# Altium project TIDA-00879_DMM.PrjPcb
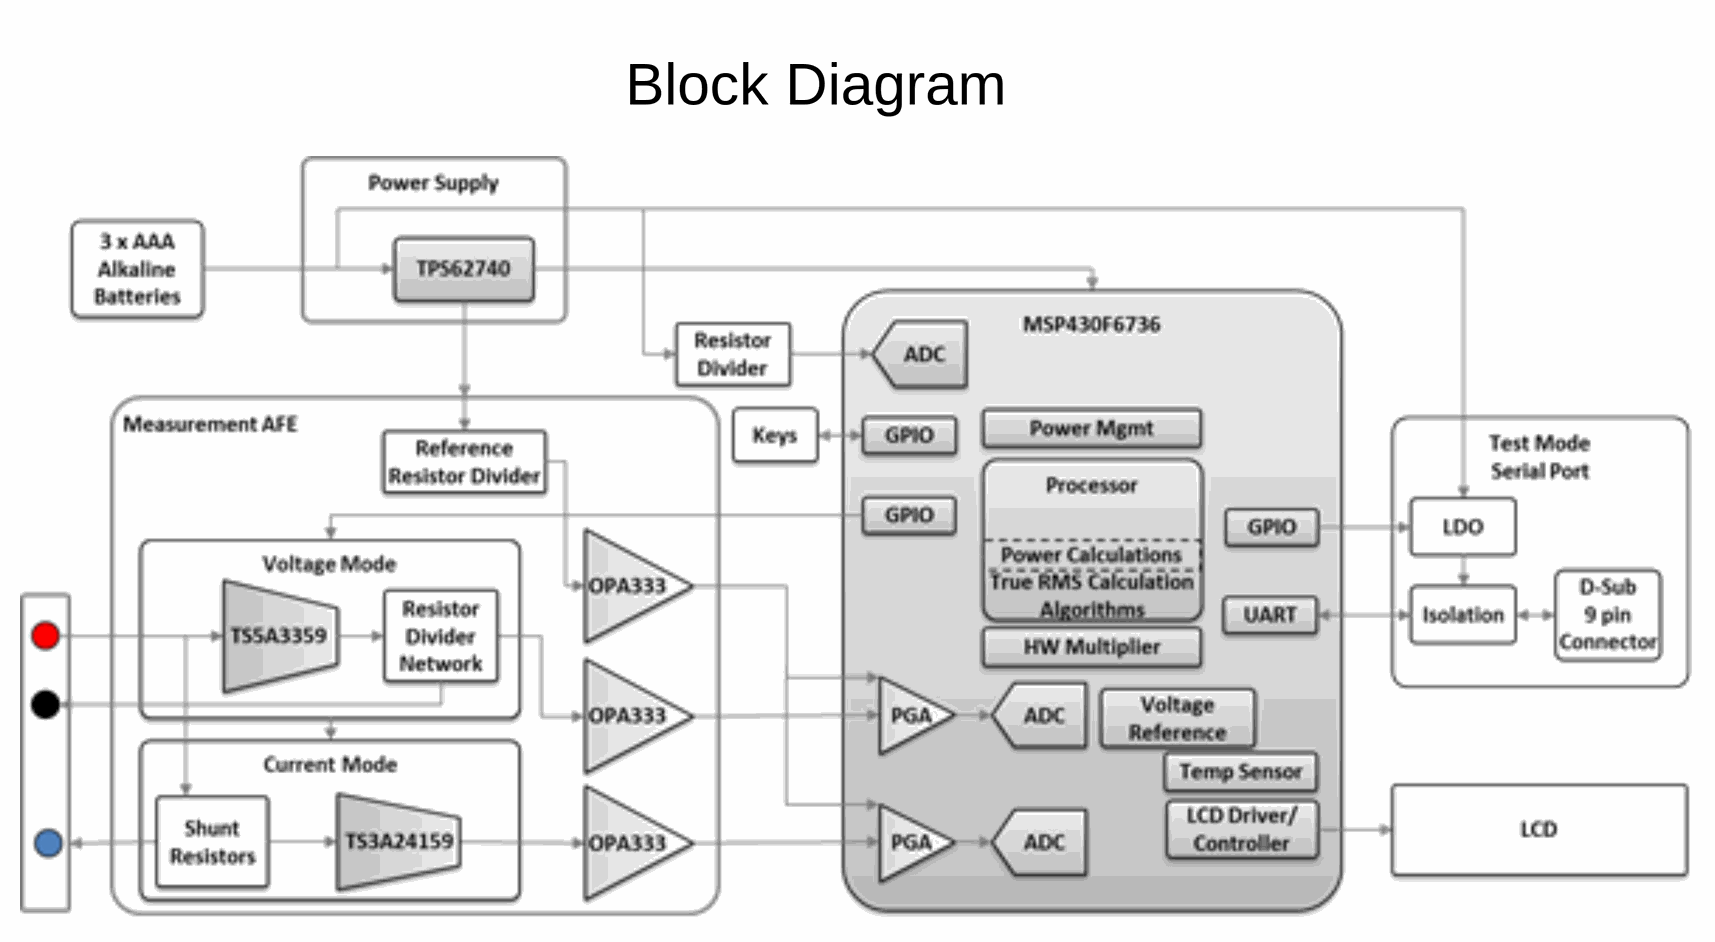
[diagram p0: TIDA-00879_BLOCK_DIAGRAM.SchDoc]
TID: TIDA-00879; TechSupport: http://www.ti.com/support; SCH_Rev: A; PRJ_Title: 4.5 Digit DMM Platform Reference Design; PRJ_Number: TIDA-00879; PRJ_Engineer: Russ Rosenquist; PRJ_Customer: Public Release; PCB_Rev: A; EVM_orderable: N/A; CopyrightYear: 2016
5 sheets, 141 parts. Net scope: flat (ports and power ports of the same name join across sheets).
Board file: TIDA-00879_DMM.PcbDoc
Sheets:
  TIDA-00879_BLOCK_DIAGRAM.SchDoc
  TIDA-00879_MCU.SchDoc
  TIDA-00879_AFE.SchDoc
  TIDA-00879_TEST.SchDoc
  TIDA-00879_MISC.SchDoc

## Sheet TIDA-00879_BLOCK_DIAGRAM.SchDoc: Hardware - Miscellaneous
size 431 x 279 mm; Date: Not shown in title block; ApprovedBy: Not shown in title block; CheckedBy: Not shown in title block; Author: Not shown in title block; CompanyName: Not shown in title block; DrawnBy: Russ Rosenquist; Engineer: Not shown in title block; Organization: Not shown in title block; Address1: Not shown in title block; Address2: Not shown in title block; Address3: Not shown in title block; Address4: Not shown in title block; Revision: Use project parameter SCH_Rev; SheetNumber: 1; SheetTotal: 5; PageSetup: Record=PageOptions¦CenterHorizontal=True¦CenterVertical=True¦PrintScale=1.00¦XCorrection=1.00¦YCorrection=1.00¦PrintKind=0¦BorderSize=5000000¦LeftOffset=0¦BottomOffset=0¦Orientation=2¦PaperLength=1000¦PaperWidth=1000¦Scale=100¦PaperSource=15¦PrintQuality=600¦MediaType=1¦DitherType=10¦PaperKind=Letter¦PrintScaleMode=1

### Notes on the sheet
- Block Diagram

## Sheet TIDA-00879_MCU.SchDoc: MCU & Power Blocks
size 431 x 279 mm; Date: Not shown in title block; ApprovedBy: Not shown in title block; CheckedBy: Not shown in title block; Author: Not shown in title block; CompanyName: Not shown in title block; DrawnBy: Russ Rosenquist; Engineer: Russ Rosenquist; Organization: Not shown in title block; Address1: Not shown in title block; Address2: Not shown in title block; Address3: Not shown in title block; Address4: Not shown in title block; DocumentNumber: 1; Revision: Use project parameter SCH_Rev; SheetNumber: 2; SheetTotal: 5; PageSetup: Record=PageOptions¦CenterHorizontal=True¦CenterVertical=True¦PrintScale=1.00¦XCorrection=1.00¦YCorrection=1.00¦PrintKind=0¦BorderSize=5000000¦LeftOffset=0¦BottomOffset=0¦Orientation=2¦PaperLength=1000¦PaperWidth=1000¦Scale=100¦PaperSource=15¦PrintQuality=600¦MediaType=1¦DitherType=10¦PaperKind=Letter¦PrintScaleMode=1
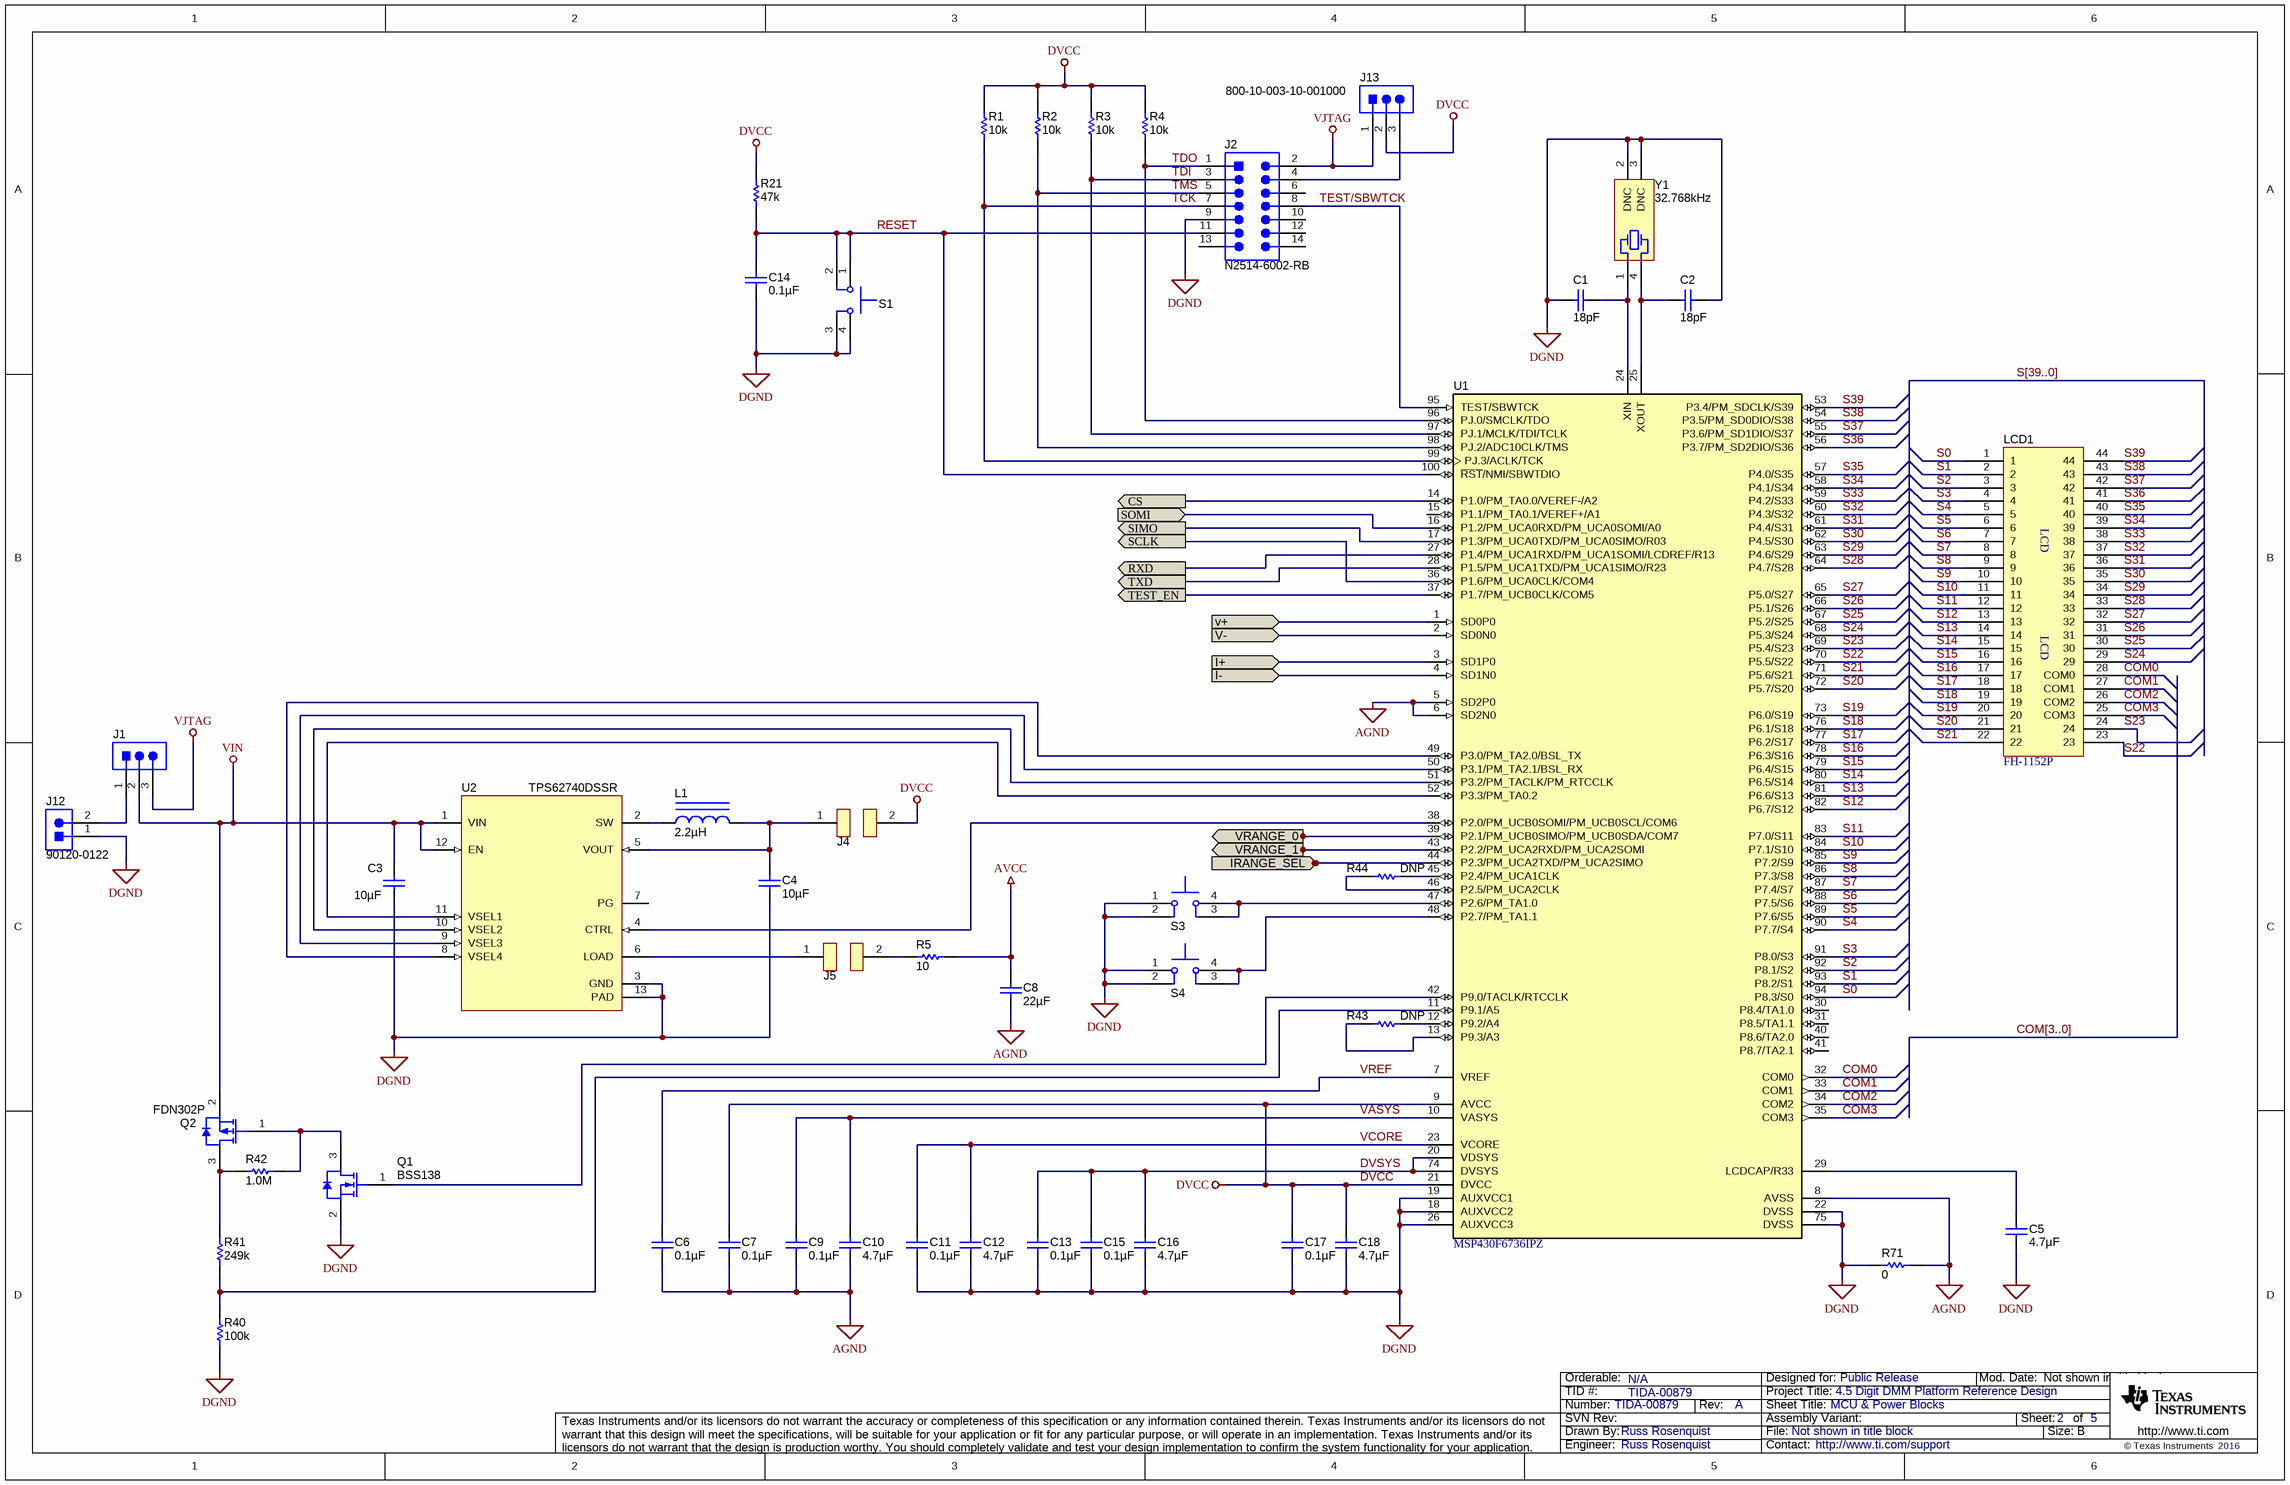
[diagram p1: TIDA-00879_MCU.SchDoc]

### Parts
C1  ValueDisplayed: 18pF  [0402]  (hidden comment: GRM1555C1H180JA01D)
C2  ValueDisplayed: 18pF  [0402]  (hidden comment: GRM1555C1H180JA01D)
C3  ValueDisplayed: 10µF  [0603]  (hidden comment: GRM188R60J106ME84)
C4  ValueDisplayed: 10µF  [0603]  (hidden comment: GRM188R60J106ME84)
C5  ValueDisplayed: 4.7µF  [0402]  (hidden comment: C1005X5R1A475K050BC)
C6  ValueDisplayed: 0.1µF  [0402]  (hidden comment: C1005X5R1A104K050BA)
C7  ValueDisplayed: 0.1µF  [0402]  (hidden comment: C1005X5R1A104K050BA)
C8  ValueDisplayed: 22µF  [0402]  (hidden comment: GRM155R60J226ME11D)
C9  ValueDisplayed: 0.1µF  [0402]  (hidden comment: C1005X5R1A104K050BA)
C10  ValueDisplayed: 4.7µF  [0402]  (hidden comment: C1005X5R1A475K050BC)
C11  ValueDisplayed: 0.1µF  [0402]  (hidden comment: C1005X5R1A104K050BA)
C12  ValueDisplayed: 4.7µF  [0402]  (hidden comment: C1005X5R1A475K050BC)
C13  ValueDisplayed: 0.1µF  [0402]  (hidden comment: C1005X5R1A104K050BA)
C14  ValueDisplayed: 0.1µF  [0603]  (hidden comment: 06033C104JAT2A)
C15  ValueDisplayed: 0.1µF  [0402]  (hidden comment: C1005X5R1A104K050BA)
C16  ValueDisplayed: 4.7µF  [0402]  (hidden comment: C1005X5R1A475K050BC)
C17  ValueDisplayed: 0.1µF  [0402]  (hidden comment: C1005X5R1A104K050BA)
C18  ValueDisplayed: 4.7µF  [0402]  (hidden comment: C1005X5R1A475K050BC)
J1  800-10-003-10-001000  [Mill-Max_800-10-003-10-001000]  (value not drawn)
J2  N2514-6002-RB  [3M_x2514-60xx]
J4  Used in BOM report  [JUMPER_SPCL]  (value not drawn)
J5  Used in BOM report  [JUMPER_SPCL]  (value not drawn)
J12  90120-0122  [CONN_90120-0122]
J13  800-10-003-10-001000  [Mill-Max_800-10-003-10-001000]
L1  ValueDisplayed: 2.2µH  [VLF302515MT]  (hidden comment: VLF302515MT-2R2M)
LCD1  FH-1152P  [FH-1152P]
Q1  BSS138  [SOT-23]
Q2  FDN302P  [SOT-23]
R1  ValueDisplayed: 10k  [0402]  (hidden comment: CRCW040210K0JNED)
R2  ValueDisplayed: 10k  [0402]  (hidden comment: CRCW040210K0JNED)
R3  ValueDisplayed: 10k  [0402]  (hidden comment: CRCW040210K0JNED)
R4  ValueDisplayed: 10k  [0402]  (hidden comment: CRCW040210K0JNED)
R5  ValueDisplayed: 10  [0402]  (hidden comment: CRCW040210R0JNED)
R21  ValueDisplayed: 47k  [0402]  (hidden comment: CRCW040247K0JNED)
R40  ValueDisplayed: 100k  [0402]  (hidden comment: CRCW0402100KFKED)
R41  ValueDisplayed: 249k  [0402]  (hidden comment: CRCW0402249KFKED)
R42  ValueDisplayed: 1.0M  [0402]  (hidden comment: CRCW04021M00JNED)
R43  value DNP  [0402]  (hidden comment: Used in BOM report)
R44  value DNP  [0402]  (hidden comment: Used in BOM report)
R71  ValueDisplayed: 0  [0603]  (hidden comment: CRCW06030000Z0EA)
S1  EVQ-PAD04M  [SW_EVQ-PAD04M]  (value not drawn)
S3  EVQ-PAD04M  [SW_EVQ-PAD04M]  (value not drawn)
S4  EVQ-PAD04M  [SW_EVQ-PAD04M]  (value not drawn)
U1  MSP430F6736IPZ  [PZ0100A_N]
U2  TPS62740DSSR  [DSS0012A]
Y1  Frequency: 32.768kHz  [XTAL_MC-306]  (hidden comment: MC-306 32.768K-E3:ROHS)

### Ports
CS (out), I+ (in), I- (in), IRANGE_SEL (out), RXD, SCLK (out), SIMO, SOMI (in), TEST_EN, TXD, v+ (in), V- (in), VRANGE_0 (out), VRANGE_1 (out)

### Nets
AGND: C6.2 C7.2 C8.1 C9.2 C10.1 R71.1 U1.5(SD2P0) U1.6(SD2N0) U1.8(AVSS)
AVCC: C8.2 R5.2
DGND: C1.1 C2.2 C3.2 C4.2 C5.1 C11.2 C12.2 C13.2 C14.2 C15.2 C16.1 C17.2 C18.1 J2.9 J12.1 Q1.2(S) R40.1 R71.2 S1.3 S1.4 S3.1 S3.2 S4.1 S4.2 U1.18(AUXVCC2) U1.19(AUXVCC1) U1.22(DVSS) U1.26(AUXVCC3) U1.75(DVSS) U2.3(GND) U2.13(PAD) Y1.2(DNC) Y1.3(DNC)
DVCC: C7.1 C17.1 C18.2 J4.2 J13.2 R1.2 R2.2 R3.2 R4.2 R21.2 U1.9(AVCC) U1.21(DVCC)
VIN: C3.1 J1.2 Q2.2(S) U2.1(VIN) U2.12(EN)
VJTAG: J1.3 J2.2 J13.1
COM0: LCD1.28(COM0) U1.32(COM0)
COM1: LCD1.27(COM1) U1.33(COM1)
COM2: LCD1.26(COM2) U1.34(COM2)
COM3: LCD1.25(COM3) U1.35(COM3)
CS: U1.14(P1.0/PM_TA0.0/VEREF-/A2) ; port CS
DVSYS: C13.1 C15.1 C16.2 U1.20(VDSYS) U1.74(DVSYS)
I+: U1.3(SD1P0) ; port I+
I-: U1.4(SD1N0) ; port I-
IRANGE_SEL: U1.44(P2.3/PM_UCA2TXD/PM_UCA2SIMO) ; port IRANGE_SEL
RESET: C14.1 J2.11 R21.1 S1.1 S1.2 U1.100(~{RST}/NMI/SBWTDIO)
RXD: U1.27(P1.4/PM_UCA1RXD/PM_UCA1SOMI/LCDREF/R13) ; port RXD
S0: LCD1.1 U1.94(P8.3/S0)
S1: LCD1.2 U1.93(P8.2/S1)
S2: LCD1.3 U1.92(P8.1/S2)
S3: LCD1.4 U1.91(P8.0/S3)
S4: LCD1.5 U1.90(P7.7/S4)
S5: LCD1.6 U1.89(P7.6/S5)
S6: LCD1.7 U1.88(P7.5/S6)
S7: LCD1.8 U1.87(P7.4/S7)
S8: LCD1.9 U1.86(P7.3/S8)
S9: LCD1.10 U1.85(P7.2/S9)
S10: LCD1.11 U1.84(P7.1/S10)
S11: LCD1.12 U1.83(P7.0/S11)
S12: LCD1.13 U1.82(P6.7/S12)
S13: LCD1.14 U1.81(P6.6/S13)
S14: LCD1.15 U1.80(P6.5/S14)
S15: LCD1.16 U1.79(P6.4/S15)
S16: LCD1.17 U1.78(P6.3/S16)
S17: LCD1.18 U1.77(P6.2/S17)
S18: LCD1.19 U1.76(P6.1/S18)
S19: LCD1.20 U1.73(P6.0/S19)
S20: LCD1.21 U1.72(P5.7/S20)
S21: LCD1.22 U1.71(P5.6/S21)
S22: LCD1.23 U1.70(P5.5/S22)
S23: LCD1.24 U1.69(P5.4/S23)
S24: LCD1.29 U1.68(P5.3/S24)
S25: LCD1.30 U1.67(P5.2/S25)
S26: LCD1.31 U1.66(P5.1/S26)
S27: LCD1.32 U1.65(P5.0/S27)
S28: LCD1.33 U1.64(P4.7/S28)
S29: LCD1.34 U1.63(P4.6/S29)
S30: LCD1.35 U1.62(P4.5/S30)
S31: LCD1.36 U1.61(P4.4/S31)
S32: LCD1.37 U1.60(P4.3/S32)
S33: LCD1.38 U1.59(P4.2/S33)
S34: LCD1.39 U1.58(P4.1/S34)
S35: LCD1.40 U1.57(P4.0/S35)
S36: LCD1.41 U1.56(P3.7/PM_SD2DIO/S36)
S37: LCD1.42 U1.55(P3.6/PM_SD1DIO/S37)
S38: LCD1.43 U1.54(P3.5/PM_SD0DIO/S38)
S39: LCD1.44 U1.53(P3.4/PM_SDCLK/S39)
SCLK: U1.36(P1.6/PM_UCA0CLK/COM4) ; port SCLK
SIMO: U1.17(P1.3/PM_UCA0TXD/PM_UCA0SIMO/R03) ; port SIMO
SOMI: U1.16(P1.2/PM_UCA0RXD/PM_UCA0SOMI/A0) ; port SOMI
TCK: J2.7 R1.1 U1.99(PJ.3/ACLK/TCK)
TDI: J2.3 R3.1 U1.97(PJ.1/MCLK/TDI/TCLK)
TDO: J2.1 R4.1 U1.96(PJ.0/SMCLK/TDO)
TEST/SBWTCK: J2.8 U1.95(TEST/SBWTCK)
TEST_EN: U1.37(P1.7/PM_UCB0CLK/COM5) ; port TEST_EN
TMS: J2.5 R2.1 U1.98(PJ.2/ADC10CLK/TMS)
TXD: U1.28(P1.5/PM_UCA1TXD/PM_UCA1SIMO/R23) ; port TXD
v+: U1.1(SD0P0) ; port v+
V-: U1.2(SD0N0) ; port V-
VASYS: C9.1 C10.2 U1.10(VASYS)
VCORE: C11.1 C12.1 U1.23(VCORE)
VRANGE_0: U1.39(P2.1/PM_UCB0SIMO/PM_UCB0SDA/COM7) ; port VRANGE_0
VRANGE_1: U1.43(P2.2/PM_UCA2RXD/PM_UCA2SOMI) ; port VRANGE_1
VREF: C6.1 U1.7(VREF)
NetC1_2: C1.2 U1.24(XIN) Y1.1
NetC2_1: C2.1 U1.25(XOUT) Y1.4
NetC4_1: C4.1 J4.1 L1.2 U2.5(VOUT)
NetC5_2: C5.2 U1.29(LCDCAP/R33)
NetJ1_1: J1.1 J12.2
NetJ2_4: J2.4 J13.3
NetJ5_1: J5.1 U2.6(LOAD)
NetJ5_2: J5.2 R5.1
NetL1_1: L1.1 U2.2(SW)
NetQ1_1: Q1.1(G) U1.42(P9.0/TACLK/RTCCLK)
NetQ1_3: Q1.3(D) Q2.1(G) R42.1
NetQ2_3: Q2.3(D) R41.2 R42.2
NetR40_2: R40.2 R41.1 U1.11(P9.1/A5)
NetR43_1: R43.1 U1.13(P9.3/A3)
NetR43_2: R43.2 U1.12(P9.2/A4)
NetR44_1: R44.1 U1.46(P2.5/PM_UCA2CLK)
NetR44_2: R44.2 U1.45(P2.4/PM_UCA1CLK)
NetS3_3: S3.3 S3.4 U1.47(P2.6/PM_TA1.0)
NetS4_3: S4.3 S4.4 U1.48(P2.7/PM_TA1.1)
NetU1_38: U1.38(P2.0/PM_UCB0SOMI/PM_UCB0SCL/COM6) U2.4(CTRL)
NetU1_49: U1.49(P3.0/PM_TA2.0/BSL_TX) U2.8(VSEL4)
NetU1_50: U1.50(P3.1/PM_TA2.1/BSL_RX) U2.9(VSEL3)
NetU1_51: U1.51(P3.2/PM_TACLK/PM_RTCCLK) U2.10(VSEL2)
NetU1_52: U1.52(P3.3/PM_TA0.2) U2.11(VSEL1)

Not connected (* = marked no-connect by the designer): J2 6 10 12 13 14; U1 15(P1.1/PM_TA0.1/VEREF+/A1) 30(P8.4/TA1.0) 31(P8.5/TA1.1) 40(P8.6/TA2.0) 41(P8.7/TA2.1); U2 7(PG)

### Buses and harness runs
bus COM[3..0]
bus S[39..0]

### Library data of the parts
C1 C2 = GRM1555C1H180JA01D: CAP, CERM, 18 pF, 50 V, +/- 5%, C0G/NP0, 0402; Manufacturer: MuRata; Polarized: N; CompType: Capacitor; Value: 18pF; U/M: EA; Cap_F: 0.000000000018; Tolerance_%: 5; Value1: Unknown; VDC_V: 50; Value2: 50V; TaMin_C: -55; TaMax_C: 125; AEC Category: Q200
C3 C4 = GRM188R60J106ME84: CAP, CERM, 10 µF, 6.3 V, +/- 20%, X5R, 0603; Manufacturer: MuRata; Polarized: N; CompType: Capacitor; Value: 10uF; U/M: EA; Cap_F: 0.00001; Tolerance_%: 20; Value1: Unknown; VDC_V: 6.3; Value2: 6.3V; TaMin_C: -55; TaMax_C: 85; AEC Category: Q200
C5 C10 C12 C16 C18 = C1005X5R1A475K050BC: CAP, CERM, 4.7 µF, 10 V, +/- 10%, X5R, 0402; Manufacturer: TDK; Polarized: N; CompType: Capacitor; Value: 4.7uF; U/M: EA; Cap_F: 0.0000047; Tolerance_%: 10; Value1: Unknown; Value2: 10V; TaMin_C: -55; TaMax_C: 85; AEC Category: Q200
C6 C7 C9 C11 C13 C15 C17 = C1005X5R1A104K050BA: CAP, CERM, 0.1 µF, 10 V, +/- 10%, X5R, 0402; Manufacturer: TDK; Polarized: N; CompType: Capacitor; Value: 0.1uF; U/M: EA; Cap_F: 0.0000001; Tolerance_%: 10; Value1: Unknown; Value2: 10V; TaMin_C: -55; TaMax_C: 85; AEC Category: Q200
C8 = GRM155R60J226ME11D: CAP, CERM, 22 µF, 6.3 V, +/- 20%, X5R, 0402; Manufacturer: MuRata; Polarized: N; CompType: Capacitor; Value: 22uF; U/M: EA; Cap_F: 0.000022; Tolerance_%: 20; Value1: Unknown; VDC_V: 6.3; Value2: 6.3V; TaMin_C: -55; TaMax_C: 85; AEC Category: Q200
C14 = 06033C104JAT2A: CAP, CERM, 0.1 µF, 25 V, +/- 5%, X7R, 0603; Manufacturer: AVX; Polarized: N; CompType: Capacitor; Value: 0.1uF; U/M: EA; Cap_F: 0.0000001; Tolerance_%: 5; ESR_ohm: 0.05; Value1: 0.05 ohm; VDC_V: 25; Value2: 25V; TaMin_C: -55; TaMax_C: 125; AEC Category: Q200
J1 J13 = 800-10-003-10-001000: Header, 100mil, 3x1, TH; Manufacturer: Mill-Max; SymbolCreator: a0799628
J2 = N2514-6002-RB: Header (shrouded), 100mil, 7x2, Gold, TH; Manufacturer: 3M; SymbolCreator: a0412235
J4 J5 = Jumper_SPCL: SymbolVersion: use current date i.e. 2008-05-20; SymbolCreator: Use a-id; CompType: Used in some BOM reports.  Useful for finding later.; U/M: EA, IN, or GM
J12 = 90120-0122: Header, 100mil, 2x1, Tin, TH; Manufacturer: Molex; SymbolCreator: a0412235
L1 = VLF302515MT-2R2M: Inductor, Shielded, Ferrite, 2.2 µH, 1.57 A, 0.042 ohm, SMD; Manufacturer: TDK; Value: 2.2uH; Ind_H: 2.2E-6; Imax_A: 1.57; Irms: 2.71A @ 40C rise; Isat: 1.57A @ 30% inductance drop; DCR_ohm: 0.042; Value2: 1.57A; AEC Category: Q200
LCD1 = FH-1152P: 160 segment LCD; PartNumber: Supplied by TI; Manufacturer: Custom
Q1 = BSS138: MOSFET, N-CH, 50 V, 0.22 A, SOT-23; Manufacturer: Fairchild Semiconductor; Alternate Manufacturer: None; U/M: EA; ChType: N; Value: 50V; VdsMax_V: 50; Value1: 6 ohm; Rdson45_ohm: 6; Value2: 1.7 nC; QgTyp_nC: 1.7; Vgs_V: 20; IdsMax_A: 0.22; AEC Category: Q101
Q2 = FDN302P: MOSFET, P-CH, -20 V, -2.4 A, SOT-23; Manufacturer: Fairchild Semiconductor; Alternate Manufacturer: None; U/M: EA; ChType: P; Value: -20V; Value1: 0.055 ohm; Rdson45_ohm: 0.055; Value2: 9 nC; QgTyp_nC: 9; Vgs_V: -12; AEC Category: Q101
R1-R4 = CRCW040210K0JNED: RES, 10 k, 5%, 0.063 W, 0402; Manufacturer: Vishay-Dale; CompType: Resistor; Value: 10k; Res_ohm: 10000; Value_Code: 10k0; Tolerance_%: 5; Power_W: 0.063; Value2: 0.063W; VDC_V: 50; TempCo: 200 ppm/C; EIA_Code: E24; U/M: EA; AEC Category: Q200
R5 = CRCW040210R0JNED: RES, 10, 5%, 0.063 W, 0402; Manufacturer: Vishay-Dale; CompType: Resistor; Value: 10; Value_Code: 10R0; Tolerance_%: 5; Power_W: 0.063; Value2: 0.063W; VDC_V: 50; TempCo: 200 ppm/C; EIA_Code: E24; U/M: EA; AEC Category: Q200
R21 = CRCW040247K0JNED: RES, 47 k, 5%, 0.063 W, 0402; Manufacturer: Vishay-Dale; CompType: Resistor; Value: 47k; Res_ohm: 47000; Value_Code: 47k0; Tolerance_%: 5; Power_W: 0.063; Value2: 0.063W; VDC_V: 50; TempCo: 200 ppm/C; EIA_Code: E24; U/M: EA; AEC Category: Q200
R40 = CRCW0402100KFKED: RES, 100 k, 1%, 0.063 W, 0402; Manufacturer: Vishay-Dale; CompType: Resistor; Value: 100k; Res_ohm: 100000; Tolerance_%: 1; Power_W: 0.063; Value2: 0.063W; VDC_V: 50; TempCo: 100 ppm/C; EIA_Code: E96; U/M: EA; AEC Category: Q200
R41 = CRCW0402249KFKED: RES, 249 k, 1%, 0.063 W, 0402; Manufacturer: Vishay-Dale; CompType: Resistor; Value: 249k; Res_ohm: 249000; Tolerance_%: 1; Power_W: 0.063; Value2: 0.063W; VDC_V: 50; TempCo: 100 ppm/C; EIA_Code: E96; U/M: EA; AEC Category: Q200
R42 = CRCW04021M00JNED: RES, 1.0 M, 5%, 0.063 W, 0402; Manufacturer: Vishay-Dale; CompType: Resistor; Value: 1.0Meg; Res_ohm: 1000000; Value_Code: 1M00; Tolerance_%: 5; Power_W: 0.063; Value2: 0.063W; VDC_V: 50; TempCo: 200 ppm/C; EIA_Code: E24; U/M: EA; AEC Category: Q200
R43 R44 = Resistor: RES, 0402 footprint placeholder; U/M: EA
R71 = CRCW06030000Z0EA: RES, 0, 5%, 0.1 W, 0603; Manufacturer: Vishay-Dale; CompType: Resistor; Value: 0; Value_Code: 0000; Tolerance_%: 5; Power_W: 0.1; Value2: 0.1W; VDC_V: 75; TempCo: 200 ppm/C; EIA_Code: E24; U/M: EA; AEC Category: Q200
S1 S3 S4 = EVQ-PAD04M: SWITCH TACTILE SPST-NO 0.02A 15V, TH; Manufacturer: Panasonic; SymbolCreator: a0411947; VDC_V: 15; SwitchFunction: Off-On; PositionCount: 1; CurrentRating_mA: 20
U1 = MSP430F6736IPZ: 25 MHz Mixed Signal Microcontroller with 128 KB Flash, 8192 B SRAM and 72 GPIOs, -40 to 85 degC, 100-pin QFP (PZ), Green (RoHS & no Sb/Br); Alternate Manufacturer: Texas Instruments; Alternate PartNumber: Equivalent; ADC: 10-bit SAR; ADC Channels: 8; Brown Out Reset: Yes; DMA: 3; Flash(KB): 128; Frequency(MHz): 25; GPIO: 72; LCD Segments: 320; Multiplier: 32x32; Pin/Package: 100LQFP, 80LQFP; Real-Time Clock: Yes, with battery backup; SRAM(B): 8192; SubFamily: 6 Series with LCD; Timers - 16-bit: 4; USCI_B (I2C & SPI): 1
U2 = TPS62740DSSR: 360nA IQ Step Down Converter for Low Power Applications, DSS0012A; Alternate PartNumber: TPS62740DSST; Manufacturer: Texas Instruments; SymbolCreator: Altium; CompType: IC; U/M: EA
Y1 = MC-306 32.768K-E3:ROHS: Crystal, 32.768kHz, 6pF, SMD; Manufacturer: Epson; SymbolCreator: a0411947; U/M: EA; TaMin_C: -40; TaMax_C: 85; Frequency Stability: ±20ppm

## Sheet TIDA-00879_AFE.SchDoc: AFE Block
size 431 x 279 mm; Date: Not shown in title block; ApprovedBy: Not shown in title block; CheckedBy: Not shown in title block; Author: Not shown in title block; CompanyName: Not shown in title block; DrawnBy: Russ Rosenquist; Engineer: Not shown in title block; Organization: Not shown in title block; Address1: Not shown in title block; Address2: Not shown in title block; Address3: Not shown in title block; Address4: Not shown in title block; DocumentNumber: 2; Revision: Use project parameter SCH_Rev; SheetNumber: 3; SheetTotal: 5; PageSetup: Record=PageOptions¦CenterHorizontal=True¦CenterVertical=True¦PrintScale=0.62¦XCorrection=1.00¦YCorrection=1.00¦PrintKind=0¦BorderSize=5000000¦LeftOffset=0¦BottomOffset=0¦Orientation=2¦PaperLength=1000¦PaperWidth=1000¦Scale=100¦PaperSource=15¦PrintQuality=600¦MediaType=1¦DitherType=10¦PrintScaleMode=1¦PaperKind=Letter
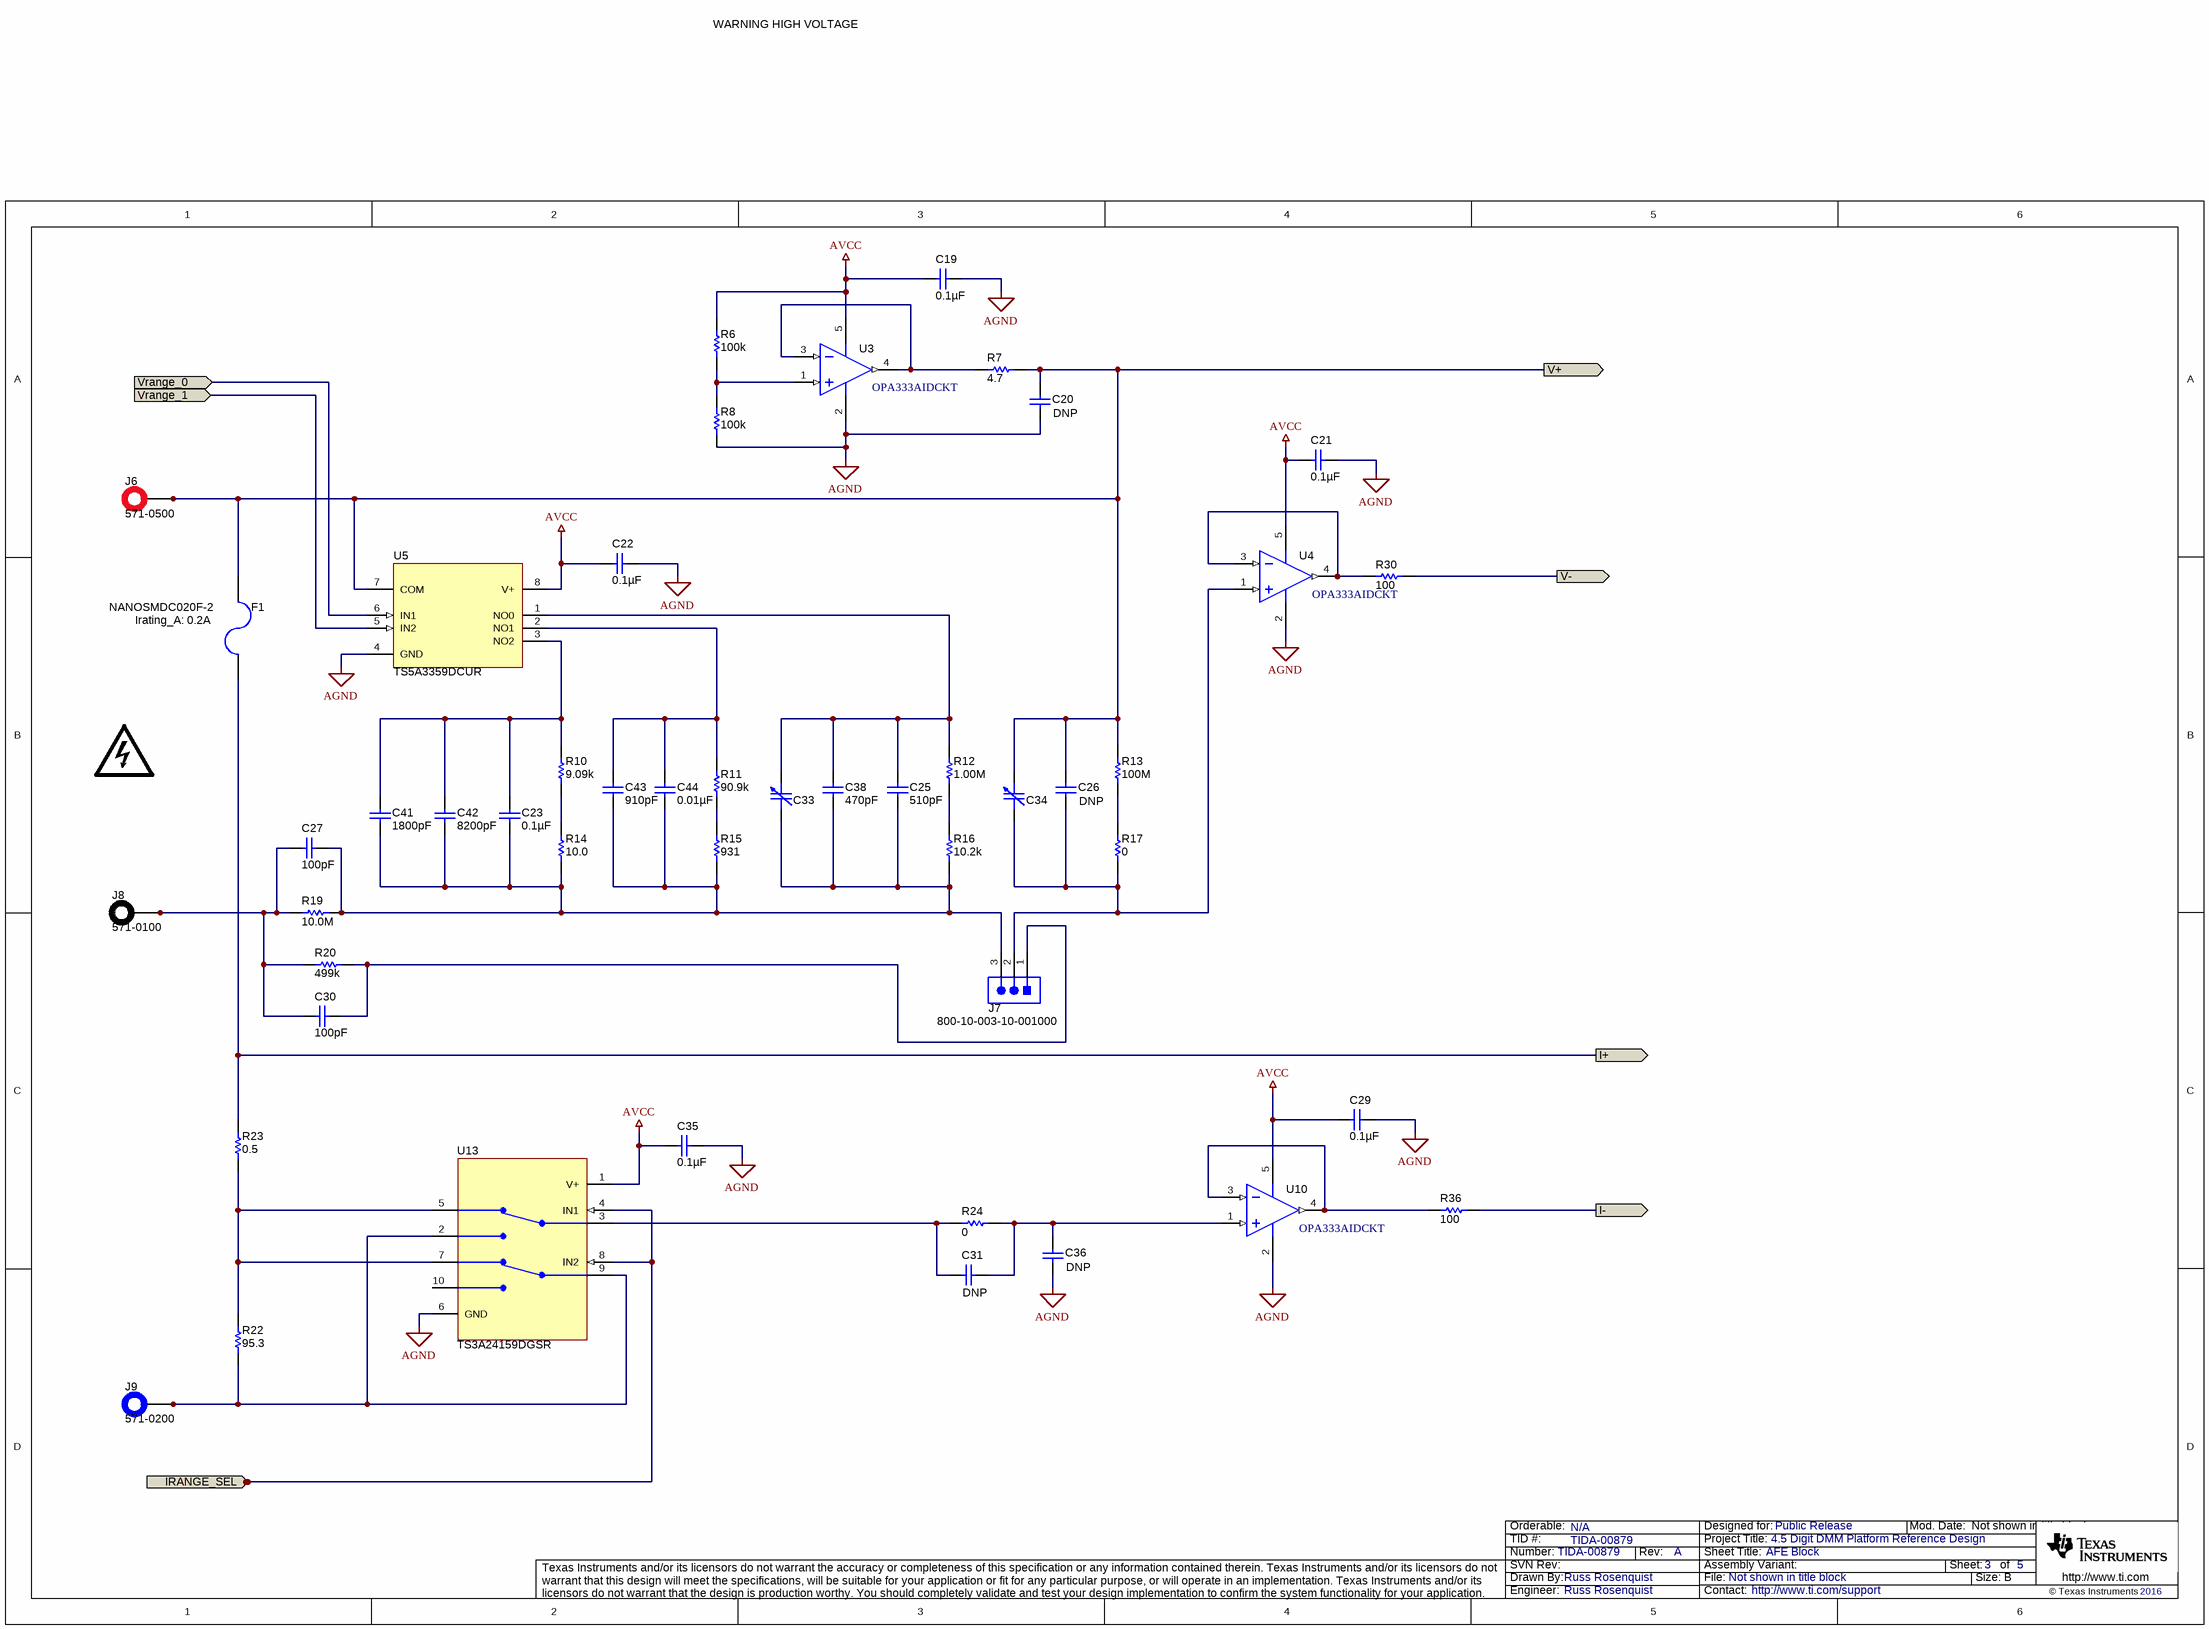
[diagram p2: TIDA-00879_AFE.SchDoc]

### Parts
C19  ValueDisplayed: 0.1µF  [0402]  (hidden comment: C1005X5R1A104K050BA)
C20  value DNP  [0603]  (hidden comment: Used in BOM Report)
C21  ValueDisplayed: 0.1µF  [0402]  (hidden comment: C1005X5R1A104K050BA)
C22  ValueDisplayed: 0.1µF  [0402]  (hidden comment: C1005X5R1A104K050BA)
C23  ValueDisplayed: 0.1µF  [0603]  (hidden comment: C0603C104J4RACTU)
C25  ValueDisplayed: 510pF  [0402]  (hidden comment: GRM1555C1H511GA01D)
C26  value DNP  [0402]  (hidden comment: Used in BOM report)
C27  ValueDisplayed: 100pF  [0603]  (hidden comment: C1608C0G2A101F080AA)
C29  ValueDisplayed: 0.1µF  [0402]  (hidden comment: C1005X5R1A104K050BA)
C30  ValueDisplayed: 100pF  [0402]  (hidden comment: GRM1555C1H101FA01D)
C31  value DNP  [0402]  (hidden comment: Used in BOM Report)
C33  TZB4R200AB10B00  [Murata_TZB4_A]  (value not drawn)
C34  TZB4R200AB10B00  [Murata_TZB4_A]  (value not drawn)
C35  ValueDisplayed: 0.1µF  [0402]  (hidden comment: C1005X5R1A104K050BA)
C36  value DNP  [0402]  (hidden comment: Used in BOM report)
C38  ValueDisplayed: 470pF  [0805_HV]  (hidden comment: 08055A471FAT2A)
C41  ValueDisplayed: 1800pF  [0402]  (hidden comment: GRM1557U1A182JA01D)
C42  ValueDisplayed: 8200pF  [0603]  (hidden comment: C1608C0G1E822J)
C43  ValueDisplayed: 910pF  [0603]  (hidden comment: C0603C911J5GACTU)
C44  ValueDisplayed: 0.01µF  [0805_HV]  (hidden comment: C0805C103F1GACTU)
F1  NANOSMDC020F-2  Irating_A: 0.2A  [FUSE_NANO02]
J6  571-0500  [571-0500]
J7  800-10-003-10-001000  [Mill-Max_800-10-003-10-001000]
J8  571-0100  [571-0100]
J9  571-0200  [571-0200]
LOGO8  WARNING HIGH VOLTAGE  [IEC_HighVoltage_Small]  (no BOM)
R6  ValueDisplayed: 100k  [0402]  (hidden comment: CRCW0402100KFKED)
R7  ValueDisplayed: 4.7  [0402]  (hidden comment: CRCW04024R70JNED)
R8  ValueDisplayed: 100k  [0402]  (hidden comment: CRCW0402100KFKED)
R10  ValueDisplayed: 9.09k  [0402]  (hidden comment: CRCW04029K09FKED)
R11  ValueDisplayed: 90.9k  [0402]  (hidden comment: CRCW040290K9FKED)
R12  ValueDisplayed: 1.00M  [0402]  (hidden comment: CRCW04021M00FKED)
R13  ValueDisplayed: 100M  [0603]  (hidden comment: CRCW0603100MJPEAHR)
R14  ValueDisplayed: 10.0  [0402]  (hidden comment: CRCW040210R0FKED)
R15  ValueDisplayed: 931  [0402]  (hidden comment: CRCW0402931RFKED)
R16  ValueDisplayed: 10.2k  [0402]  (hidden comment: CRCW040210K2FKED)
R17  ValueDisplayed: 0  [0402]  (hidden comment: CRCW04020000Z0ED)
R19  ValueDisplayed: 10.0M  [1206]  (hidden comment: CRHV1206AF10M0FKE5)
R20  ValueDisplayed: 499k  [0402]  (hidden comment: CRCW0402499KFKED)
R22  ValueDisplayed: 95.3  [2512]  (hidden comment: CRCW251295R3FKEG)
R23  ValueDisplayed: 0.5  [0603]  (hidden comment: RL0603FR-070R5L)
R24  ValueDisplayed: 0  [0402]  (hidden comment: CRCW04020000Z0ED)
R30  ValueDisplayed: 100  [0402]  (hidden comment: CRCW0402100RFKED)
R36  ValueDisplayed: 100  [0402]  (hidden comment: CRCW0402100RFKED)
U3  OPA333AIDCKT  [DCK0005A_N]
U4  OPA333AIDCKT  [DCK0005A_N]
U5  TS5A3359DCUR  [DCU0008A_N]
U10  OPA333AIDCKT  [DCK0005A_N]
U13  TS3A24159DGSR  [DGS0010A_N]

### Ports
I+ (out), I- (out), IRANGE_SEL (out), V+ (out), V- (out), Vrange_0 (in), Vrange_1 (in)

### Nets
AGND: C19.2 C20.2 C21.2 C22.2 C29.2 C35.2 C36.1 R8.1 U3.2(V-) U4.2(V-) U5.4(GND) U10.2(V-) U13.6(GND)
AVCC: C19.1 C21.1 C22.1 C29.1 C35.1 R6.2 U3.5(V+) U4.5(V+) U5.8(V+) U10.5(V+) U13.1(V+)
I+: F1.2 R23.2 ; port I+
I-: R36.1 ; port I-
IRANGE_SEL: U13.4(IN1) U13.8(IN2) ; port IRANGE_SEL
v+: C20.1 C26.2 C34.2 F1.1 J6.1 J6.2 R7.1 R13.2 U5.7(COM) ; port V+
V-: R30.1 ; port V-
VRANGE_0: U5.6(IN1) ; port Vrange_0
VRANGE_1: U5.5(IN2) ; port Vrange_1
NetC23_1: C23.1 C25.1 C27.2 C33.1 C38.1 C41.1 C42.1 C43.1 C44.1 J7.3 R14.1 R15.1 R16.1 R19.2
NetC23_2: C23.2 C41.2 C42.2 R10.2 U5.3(NO2)
NetC25_2: C25.2 C33.2 C38.2 R12.2 U5.1(NO0)
NetC26_1: C26.1 C34.1 J7.2 R17.1 U4.1(IN+)
NetC27_1: C27.1 C30.1 J8.1 J8.2 R19.1 R20.1
NetC30_2: C30.2 J7.1 R20.2
NetC31_1: C31.1 R24.2 U13.3(COM1)
NetC31_2: C31.2 C36.2 R24.1 U10.1(IN+)
NetC43_2: C43.2 C44.2 R11.2 U5.2(NO1)
NetJ9_1: J9.1 J9.2 R22.1 U13.2(NO1) U13.9(COM2)
NetR6_1: R6.1 R8.2 U3.1(IN+)
NetR7_2: R7.2 U3.3(IN-) U3.4(OUT)
NetR10_1: R10.1 R14.2
NetR11_1: R11.1 R15.2
NetR12_1: R12.1 R16.2
NetR13_1: R13.1 R17.2
NetR22_2: R22.2 R23.1 U13.5(NC1) U13.7(NC2)
NetR30_2: R30.2 U4.3(IN-) U4.4(OUT)
NetR36_2: R36.2 U10.3(IN-) U10.4(OUT)

Not connected (* = marked no-connect by the designer): U13 10(NO2)

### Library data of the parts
C19 C21 C22 C29 C35 = C1005X5R1A104K050BA: as C6 on sheet TIDA-00879_MCU
C20 = Capacitor: Cap, 0603 footprint placeholder; Polarized: N; U/M: EA
C23 = C0603C104J4RACTU: CAP, CERM, 0.1 µF, 16 V, +/- 5%, X7R, 0603; Manufacturer: Kemet; Polarized: N; CompType: Capacitor; Value: 0.1uF; U/M: EA; Cap_F: 0.0000001; Tolerance_%: 5; Value1: Unknown; VDC_V: 16; Value2: 16V; TaMin_C: -55; TaMax_C: 125; AEC Category: Q200
C25 = GRM1555C1H511GA01D: CAP, CERM, 510 pF, 50 V, +/- 2%, C0G/NP0, 0402; Manufacturer: MuRata; Polarized: N; CompType: Capacitor; Value: 510pF; U/M: EA; Cap_F: 0.00000000051; Tolerance_%: 2; Value1: Unknown; VDC_V: 50; Value2: 50V; TaMin_C: -55; TaMax_C: 125; AEC Category: Q200
C26 C31 C36 = Capacitor: Cap, 0402 footprint placeholder; Polarized: N; U/M: EA
C27 = C1608C0G2A101F080AA: CAP, CERM, 100 pF, 100 V, +/- 1%, C0G/NP0, 0603; Manufacturer: TDK; Polarized: N; CompType: Capacitor; Value: 100pF; U/M: EA; Cap_F: 0.0000000001; Tolerance_%: 1; Value1: Unknown; VDC_V: 100; Value2: 100V; TaMin_C: -55; TaMax_C: 125; AEC Category: Q200
C30 = GRM1555C1H101FA01D: CAP, CERM, 100 pF, 50 V, +/- 1%, C0G/NP0, 0402; Manufacturer: MuRata; Polarized: N; CompType: Capacitor; Value: 100pF; U/M: EA; Cap_F: 0.0000000001; Tolerance_%: 1; Value1: Unknown; VDC_V: 50; Value2: 50V; TaMin_C: -55; TaMax_C: 125; AEC Category: Q200
C33 C34 = TZB4R200AB10B00: Ceramic Trimmer Capacitor, 4.5 to 20 pF, SMT; Manufacturer: MuRata; SymbolCreator: Altium; Value: 4.5 - 20pF
C38 = 08055A471FAT2A: CAP, CERM, 470 pF, 50 V, +/- 1%, C0G/NP0, 0805; Manufacturer: AVX; Polarized: N; CompType: Capacitor; Value: 470pF; U/M: EA; Cap_F: 0.00000000047; Tolerance_%: 1; ESR_ohm: 0.159; Value1: 0.159 ohm; VDC_V: 50; Value2: 50V; TaMin_C: -55; TaMax_C: 125; Cap_Case: 0805; AEC Category: Q200
C41 = GRM1557U1A182JA01D: CAP, CERM, 1800 pF, 10 V, +/- 5%, U2J, 0402; Manufacturer: MuRata; Polarized: N; CompType: Capacitor; Value: 1800pF; U/M: EA; Cap_F: 0.0000000018; Tolerance_%: 5; Value1: Unknown; VDC_V: 10; Value2: 10V; TaMin_C: -55; TaMax_C: 125; AEC Category: Q200
C42 = C1608C0G1E822J: CAP, CERM, 8200 pF, 25 V, +/- 5%, C0G/NP0, 0603; Manufacturer: TDK; Polarized: N; CompType: Capacitor; Value: 8200pF; U/M: EA; Cap_F: 0.0000000082; Tolerance_%: 5; Value1: Unknown; VDC_V: 25; Value2: 25V; TaMin_C: -55; TaMax_C: 125; AEC Category: Q200
C43 = C0603C911J5GACTU: CAP, CERM, 910 pF, 50 V, +/- 5%, C0G/NP0, 0603; Manufacturer: Kemet; Polarized: N; CompType: Capacitor; Value: 910pF; U/M: EA; Cap_F: 0.00000000091; Tolerance_%: 5; Value1: Unknown; VDC_V: 50; Value2: 50V; TaMin_C: -55; TaMax_C: 125; AEC Category: Q200
C44 = C0805C103F1GACTU: CAP, CERM, 0.01 µF, 100 V, +/- 1%, C0G/NP0, 0805; Manufacturer: Kemet; Polarized: N; CompType: Capacitor; Value: 0.01uF; U/M: EA; Cap_F: 0.00000001; Tolerance_%: 1; Value1: Unknown; VDC_V: 100; Value2: 100V; TaMin_C: -55; TaMax_C: 125; Cap_Case: 0805; AEC Category: Q200
F1 = NANOSMDC020F-2: Fuse, Resettable, 0.2 A, 24 VDC, SMD; Manufacturer: TE Connectivity; VDC_V: 24; Rtyp_Ohm: 1.875; SymbolCreator: a0412235
J6 = 571-0500: Standard Banana Jack, insulated, 10A, red; Manufacturer: DEM Manufacturing; CompType: Connector; SymbolCreator: codlsc; U/M: EA
J7 = 800-10-003-10-001000: as J1 on sheet TIDA-00879_MCU
J8 = 571-0100: Standard Banana Jack, insulated, 10A, black; Manufacturer: DEM Manufacturing; CompType: Connector; SymbolCreator: codlsc; U/M: EA
J9 = 571-0200: Standard Banana Jack, insulated, 10A, blue; Manufacturer: DEM Manufacturing; CompType: Connector; SymbolCreator: codlsc; U/M: EA
LOGO8 = IEC_HighVoltage: IEC 61010-1 High Voltage Warning; SymbolCreator: a0412235
R6 R8 = CRCW0402100KFKED: as R40 on sheet TIDA-00879_MCU
R7 = CRCW04024R70JNED: RES, 4.7, 5%, 0.063 W, 0402; Manufacturer: Vishay-Dale; CompType: Resistor; Value: 4.7; Value_Code: 4R70; Tolerance_%: 5; Power_W: 0.063; Value2: 0.063W; VDC_V: 50; TempCo: 200 ppm/C; EIA_Code: E24; U/M: EA; AEC Category: Q200
R10 = CRCW04029K09FKED: RES, 9.09 k, 1%, 0.063 W, 0402; Manufacturer: Vishay-Dale; CompType: Resistor; Value: 9.09k; Res_ohm: 9090; Value_Code: 9k09; Tolerance_%: 1; Power_W: 0.063; Value2: 0.063W; VDC_V: 50; TempCo: 100 ppm/C; EIA_Code: E96; U/M: EA; AEC Category: Q200
R11 = CRCW040290K9FKED: RES, 90.9 k, 1%, 0.063 W, 0402; Manufacturer: Vishay-Dale; CompType: Resistor; Value: 90.9k; Res_ohm: 90900; Value_Code: 90k9; Tolerance_%: 1; Power_W: 0.063; Value2: 0.063W; VDC_V: 50; TempCo: 100 ppm/C; EIA_Code: E96; U/M: EA; AEC Category: Q200
R12 = CRCW04021M00FKED: RES, 1.00 M, 1%, 0.063 W, 0402; Manufacturer: Vishay-Dale; CompType: Resistor; Value: 1.00Meg; Res_ohm: 1000000; Value_Code: 1M00; Tolerance_%: 1; Power_W: 0.063; Value2: 0.063W; VDC_V: 50; TempCo: 100 ppm/C; EIA_Code: E96; U/M: EA; AEC Category: Q200
R13 = CRCW0603100MJPEAHR: RES, 100 M, 5%, 0.1 W, 0603; Manufacturer: Vishay-Dale; CompType: Resistor; Value: 100Meg; Res_ohm: 100000000; Tolerance_%: 5; Power_W: 0.1; Value2: 0.1W; VDC_V: 75; TempCo: 500 ppm/C; U/M: EA; AEC Category: Q200
R14 = CRCW040210R0FKED: RES, 10.0, 1%, 0.063 W, 0402; Manufacturer: Vishay-Dale; CompType: Resistor; Value: 10.0; Res_ohm: 10; Value_Code: 10R0; Tolerance_%: 1; Power_W: 0.063; Value2: 0.063W; VDC_V: 50; TempCo: 100 ppm/C; EIA_Code: E96; U/M: EA; AEC Category: Q200
R15 = CRCW0402931RFKED: RES, 931, 1%, 0.063 W, 0402; Manufacturer: Vishay-Dale; CompType: Resistor; Value: 931; Value_Code: 931R; Tolerance_%: 1; Power_W: 0.063; Value2: 0.063W; VDC_V: 50; TempCo: 100 ppm/C; EIA_Code: E96; U/M: EA; AEC Category: Q200
R16 = CRCW040210K2FKED: RES, 10.2 k, 1%, 0.063 W, 0402; Manufacturer: Vishay-Dale; CompType: Resistor; Value: 10.2k; Res_ohm: 10200; Value_Code: 10k2; Tolerance_%: 1; Power_W: 0.063; Value2: 0.063W; VDC_V: 50; TempCo: 100 ppm/C; EIA_Code: E96; U/M: EA; AEC Category: Q200
R17 R24 = CRCW04020000Z0ED: RES, 0, 5%, 0.063 W, 0402; Manufacturer: Vishay-Dale; CompType: Resistor; Value: 0; Value_Code: 0000; Tolerance_%: 5; Power_W: 0.063; Value2: 0.063W; VDC_V: 50; TempCo: 200 ppm/C; EIA_Code: E24; U/M: EA; AEC Category: Q200
R19 = CRHV1206AF10M0FKE5: RES, 10.0 M, 1%, 0.3 W, 1206; Manufacturer: Vishay-Dale; CompType: Resistor; Value: 10.0Meg; Res_ohm: 10000000; Value_Code: 10M0; Tolerance_%: 1; Power_W: 0.3; Value2: 0.3W; VDC_V: 1500; TempCo: 100 ppm/C; EIA_Code: E96; U/M: EA; AEC Category: Q200; AEC Qualified: N
R20 = CRCW0402499KFKED: RES, 499 k, 1%, 0.063 W, 0402; Manufacturer: Vishay-Dale; CompType: Resistor; Value: 499k; Res_ohm: 499000; Tolerance_%: 1; Power_W: 0.063; Value2: 0.063W; VDC_V: 50; TempCo: 100 ppm/C; EIA_Code: E96; U/M: EA; AEC Category: Q200
R22 = CRCW251295R3FKEG: RES, 95.3, 1%, 1 W, 2512; Manufacturer: Vishay-Dale; CompType: Resistor; Value: 95.3; Value_Code: 95R3; Tolerance_%: 1; Value2: 1W; VDC_V: 500; TempCo: 100 ppm/C; EIA_Code: E96; U/M: EA; AEC Category: Q200
R23 = RL0603FR-070R5L: RES, 0.5, 1%, 0.1 W, 0603; Manufacturer: Yageo America; CompType: Resistor; Value: 0.5; Value_Code: R500; Tolerance_%: 1; Power_W: 0.1; Value2: 0.1W; TempCo: 800 ppm/C; U/M: EA; AEC Category: Q200
R30 R36 = CRCW0402100RFKED: RES, 100, 1%, 0.063 W, 0402; Manufacturer: Vishay-Dale; CompType: Resistor; Value: 100; Value_Code: 100R; Tolerance_%: 1; Power_W: 0.063; Value2: 0.063W; VDC_V: 50; TempCo: 100 ppm/C; EIA_Code: E96; U/M: EA; AEC Category: Q200
U3 U4 U10 = OPA333AIDCKT: 17 uA, MicroPower, Precision, Zero Drift CMOS Operational Amplifier, 1.8 to 5.5 V, -40 to 125 degC, 5-pin SOT23 (DCK0005A), Green (RoHS & no Sb/Br); Manufacturer: Texas Instruments; Alternate PartNumber: Equivalent; CMRR(Min)(dB): 106; IIB(Max)(pA): 200; Iq per channel(Max)(mA): 0.025; Number of Channels: 1; Offset Drift(Typ)(uV/C): 0.02; Slew Rate(Typ)(V/us): 0.16; Sub Family: Low Offset Voltage Amplifier (<=500uV), Low Power Amp (<=500uA), Low Supply Voltage Amplifier (<=2.7V), Precision Amplifier, Zero Drift Precision Amplifier; Total Supply Voltage(Max)(+5V is 5, +/-5V is 10): 5.5; Total Supply Voltage(Min)(+5V is 5, +/-5V is 10): 1.8; Vio (25C)(Max)(mV): 0.01
U5 = TS5A3359DCUR: 1-Ohm SP3T ANALOG SWITCH 5-V/3.3-V SINGLE-CHANNEL 3:1 MULTIPLEXER/DEMULTIPLEXER, DCU0008A; Alternate PartNumber: TS5A3359DCUT; Manufacturer: Texas Instruments; SymbolCreator: Altium; CompType: IC; U/M: EA
U13 = TS3A24159DGSR: 0.3-Ohm DUAL SPDT ANALOG SWITCH DUAL-CHANNEL 2:1 MULTIPLEXER/DEMULTIPLEXER, DGS0010A; Manufacturer: Texas Instruments; SymbolCreator: Altium; CompType: IC; U/M: EA

## Sheet TIDA-00879_TEST.SchDoc: Test Block
size 431 x 279 mm; VersionControl_RevNumber: 1.2; Date: Not shown in title block; ApprovedBy: Not shown in title block; CheckedBy: Not shown in title block; Author: Not shown in title block; CompanyName: Not shown in title block; DrawnBy: Russ Rosenquist; Engineer: Not shown in title block; Organization: Not shown in title block; Address1: Not shown in title block; Address2: Not shown in title block; Address3: Not shown in title block; Address4: Not shown in title block; DocumentNumber: 3; Revision: Use project parameter SCH_Rev; SheetNumber: 4; SheetTotal: 5; PageSetup: Record=PageOptions¦CenterHorizontal=True¦CenterVertical=True¦PrintScale=0.62¦XCorrection=1.00¦YCorrection=1.00¦PrintKind=0¦BorderSize=5000000¦LeftOffset=0¦BottomOffset=0¦Orientation=2¦PaperLength=1000¦PaperWidth=1000¦Scale=100¦PaperSource=15¦PrintQuality=600¦MediaType=1¦DitherType=10¦PaperKind=Letter¦PrintScaleMode=1
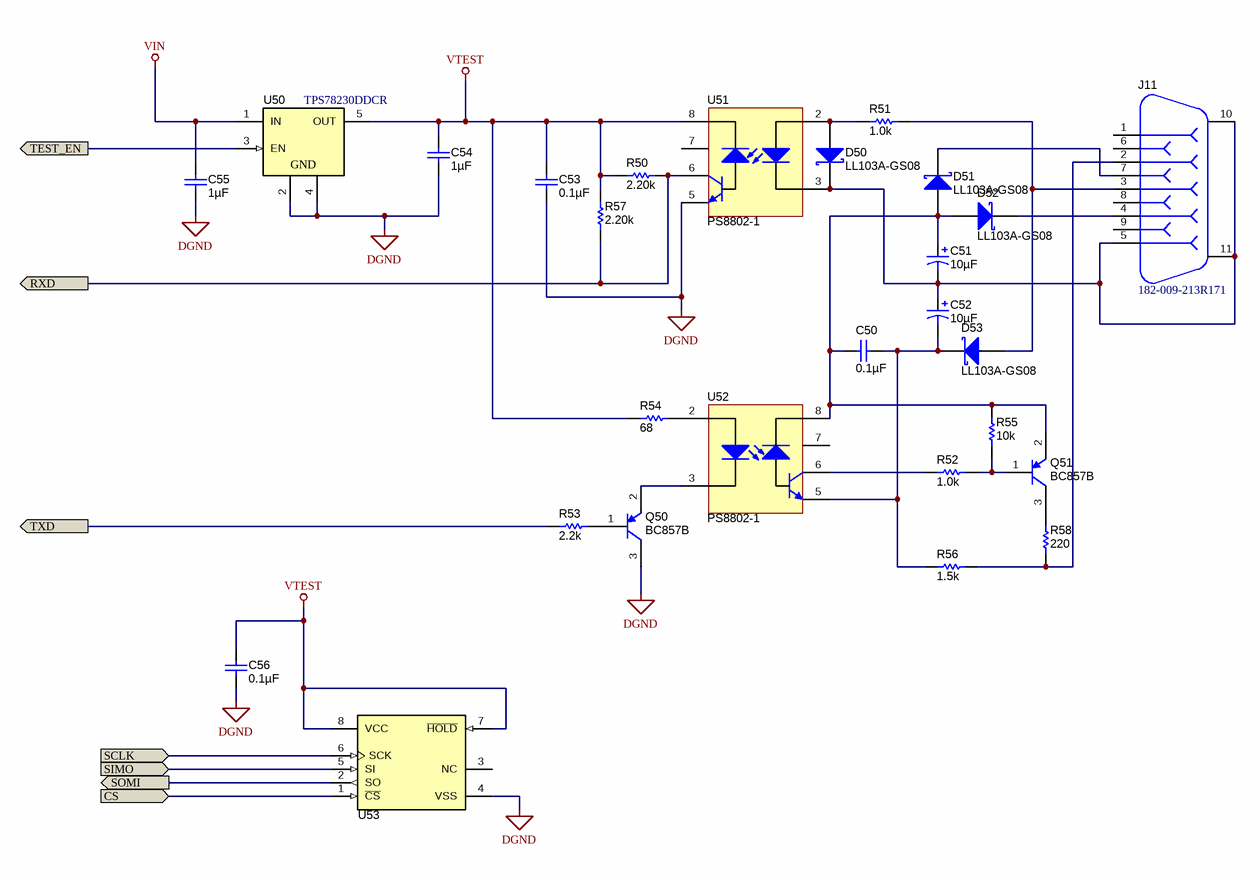
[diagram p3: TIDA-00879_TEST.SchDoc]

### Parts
C50  ValueDisplayed: 0.1µF  [0402]  (hidden comment: C1005X5R1A104K050BA)
C51  ValueDisplayed: 10µF  [3216-18]  (hidden comment: 293D106X9050E2TE3)
C52  ValueDisplayed: 10µF  [3216-18]  (hidden comment: 293D106X9050E2TE3)
C53  ValueDisplayed: 0.1µF  [0402]  (hidden comment: C1005X5R1A104K050BA)
C54  ValueDisplayed: 1µF  [0603]  (hidden comment: GRM188R61A105KA61D)
C55  ValueDisplayed: 1µF  [0603]  (hidden comment: GRM188R61A105KA61D)
C56  ValueDisplayed: 0.1µF  [0402]  (hidden comment: C1005X5R1A104K050BA)
D50  LL103A-GS08  [SOD-80]
D51  LL103A-GS08  [SOD-80]
D52  LL103A-GS08  [SOD-80]
D53  LL103A-GS08  [SOD-80]
J11  182-009-213R171  [NORCOMP_182-009-213R171]
Q50  BC857B  [SOT-23]
Q51  BC857B  [SOT-23]
R50  ValueDisplayed: 2.20k  [0402]  (hidden comment: CRCW04022K20FKED)
R51  ValueDisplayed: 1.0k  [0402]  (hidden comment: CRCW04021K00JNED)
R52  ValueDisplayed: 1.0k  [0402]  (hidden comment: CRCW04021K00JNED)
R53  ValueDisplayed: 2.2k  [0402]  (hidden comment: CRCW04022K20JNED)
R54  ValueDisplayed: 68  [0402]  (hidden comment: CRCW040268R0JNED)
R55  ValueDisplayed: 10k  [0402]  (hidden comment: CRCW040210K0JNED)
R56  ValueDisplayed: 1.5k  [0402]  (hidden comment: CRCW04021K50JNED)
R57  ValueDisplayed: 2.20k  [0402]  (hidden comment: CRCW04022K20FKED)
R58  ValueDisplayed: 220  [0402]  (hidden comment: CRCW0402220RJNED)
U50  TPS78230DDCR  [DDC0005A_N]
U51  PS8802-1  [SO-8]
U52  PS8802-1  [SO-8]
U53  23K640-I/SN  [SOIC-8]  (value not drawn)

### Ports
CS (in), RXD, SCLK (in), SIMO (in), SOMI (out), TEST_EN, TXD

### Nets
DGND: C53.2 C54.2 C55.2 C56.2 Q50.3(C) U50.2(GND) U50.4(GND) U51.5 U53.4(VSS)
VIN: C55.1 U50.1(IN)
VTEST: C53.1 C54.1 C56.1 R50.1 R54.1 R57.2 U50.5(OUT) U51.8 U53.7(~{HOLD}) U53.8(VCC)
CS: U53.1(~{CS}) ; port CS
RXD: R50.2 R57.1 U51.6 ; port RXD
SCLK: U53.6(SCK) ; port SCLK
SIMO: U53.5(SI) ; port SIMO
SOMI: U53.2(SO) ; port SOMI
TEST_EN: U50.3(EN) ; port TEST_EN
TXD: R53.1 ; port TXD
NetC50_1: C50.1 C52.2(-) D53.1(K) R56.1 U52.5
NetC50_2: C50.2 C51.1(+) D51.2(A) D52.2(A) Q51.2(E) R55.2 U52.8
NetC51_2: C51.2(-) C52.1(+) D50.1(K) J11.5 J11.10 J11.11 U51.3
NetD50_2: D50.2(A) R51.1 U51.2
NetD51_1: D51.1(K) J11.7
NetD52_1: D52.1(K) J11.4
NetD53_2: D53.2(A) J11.3 R51.2
NetJ11_2: J11.2 R56.2 R58.1
NetQ50_1: Q50.1(B) R53.2
NetQ50_2: Q50.2(E) U52.3
NetQ51_1: Q51.1(B) R52.2 R55.1
NetQ51_3: Q51.3(C) R58.2
NetR52_1: R52.1 U52.6
NetR54_2: R54.2 U52.2

Not connected (* = marked no-connect by the designer): J11 1 6 8 9; U51 1 4 7; U52 1 4 7; U53 3(NC)

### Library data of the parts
C50 C53 C56 = C1005X5R1A104K050BA: as C6 on sheet TIDA-00879_MCU
C51 C52 = 293D106X9050E2TE3: CAP, TANT, 10uF, 50V, +/-10%, 0.8 ohm, 7343-43 SMD; Manufacturer: Vishay-Sprague; Polarized: Y; CompType: Capacitor; U/M: EA; Cap_F: 0.00001; Tolerance_%: 10; Value1: 0.8 ohm; VDC_V: 50; ESR_Ohm: 0.8; IRMS_A: 0.45; TaMin_C: -55; TaMax_C: 125; Cap_Case: E
C54 C55 = GRM188R61A105KA61D: CAP, CERM, 1 µF, 10 V, +/- 10%, X5R, 0603; Manufacturer: MuRata; Polarized: N; CompType: Capacitor; Value: 1uF; U/M: EA; Cap_F: 0.000001; Tolerance_%: 10; Value1: Unknown; Value2: 10V; TaMin_C: -55; TaMax_C: 85; AEC Category: Q200
D50-D53 = LL103A-GS08: Diode, Schottky, 40 V, 0.2 A, DO-213AC; Manufacturer: Vishay-Semiconductor; U/M: EA; Vf_V: 0.6; Value: 40V; Value1: 0.2A; Value2: 0.6V; Io_A: 0.2; Vr_V: 40; TJmax_C: 125; AEC Category: Q101
J11 = 182-009-213R171: CONN DB9 FEMALE R/A SOLDER TH; Manufacturer: NorComp; SymbolCreator: a0412235; CompType: Connector
Q50 Q51 = BC857C-7-F, Diodes Inc.: Transistor, PNP, 45V, 0.1A, SOT-23; Alternate Manufacturer: None; CompType: BJT; U/M: EA; PNP: 1; NPN: 0; Vceo_V: 45; Vcesat1_V: 0.075; Value: 0.075V; IcRated_A: 0.1; HfeMax: 600
R50 R57 = CRCW04022K20FKED: RES, 2.20 k, 1%, 0.063 W, 0402; Manufacturer: Vishay-Dale; CompType: Resistor; Value: 2.20k; U/M: EA; Res_ohm: 2200; Value_Code: 2k20; Tolerance_%: 1; Power_W: 0.063; Value2: 0.063W; TempCo: 100 ppm/C; AEC Category: Q200
R51 R52 = CRCW04021K00JNED: RES, 1.0 k, 5%, 0.063 W, 0402; Manufacturer: Vishay-Dale; CompType: Resistor; Value: 1.0k; U/M: EA; Res_ohm: 1000; Value_Code: 1k00; Tolerance_%: 5; Power_W: 0.063; Value2: 0.063W; VDC_V: 50; TempCo: 200 ppm/C; EIA_Code: E24; AEC Category: Q200
R53 = CRCW04022K20JNED: RES, 2.2 k, 5%, 0.063 W, 0402; Manufacturer: Vishay-Dale; CompType: Resistor; Value: 2.2k; U/M: EA; Res_ohm: 2200; Value_Code: 2k20; Tolerance_%: 5; Power_W: 0.063; Value2: 0.063W; VDC_V: 50; TempCo: 200 ppm/C; EIA_Code: E24; AEC Category: Q200
R54 = CRCW040268R0JNED: RES, 68, 5%, 0.063 W, 0402; Manufacturer: Vishay-Dale; CompType: Resistor; Value: 68; U/M: EA; Value_Code: 68R0; Tolerance_%: 5; Power_W: 0.063; Value2: 0.063W; VDC_V: 50; TempCo: 200 ppm/C; EIA_Code: E24; AEC Category: Q200
R55 = CRCW040210K0JNED: RES, 10 k, 5%, 0.063 W, 0402; Manufacturer: Vishay-Dale; CompType: Resistor; Value: 10k; U/M: EA; Res_ohm: 10000; Value_Code: 10k0; Tolerance_%: 5; Power_W: 0.063; Value2: 0.063W; VDC_V: 50; TempCo: 200 ppm/C; EIA_Code: E24; AEC Category: Q200
R56 = CRCW04021K50JNED: RES, 1.5 k, 5%, 0.063 W, 0402; Manufacturer: Vishay-Dale; CompType: Resistor; Value: 1.5k; U/M: EA; Res_ohm: 1500; Value_Code: 1k50; Tolerance_%: 5; Power_W: 0.063; Value2: 0.063W; VDC_V: 50; TempCo: 200 ppm/C; EIA_Code: E24; AEC Category: Q200
R58 = CRCW0402220RJNED: RES, 220, 5%, 0.063 W, 0402; Manufacturer: Vishay-Dale; CompType: Resistor; Value: 220; U/M: EA; Value_Code: 220R; Tolerance_%: 5; Power_W: 0.063; Value2: 0.063W; VDC_V: 50; TempCo: 200 ppm/C; EIA_Code: E24; AEC Category: Q200
U50 = TPS78230DDCR: Single Output LDO, 150 mA, Fixed 3 V Output, 2.2 to 5.5 V Input, with 0.5 uA Quiescent Current, 5-pin SOT (DDC), -40 to 125 degC, Green (RoHS & no Sb/Br); Manufacturer: Texas Instruments; Alternate PartNumber: Equivalent; Accuracy(%): 3; Dynamic Voltage Scaling: TRUE; Iout(Max)(A): 0.15; Iq(Typ)(mA): 0.0005; Rating: Catalog; SubFamily: Single Channel LDO; Vdo(Typ)(mV): 130; Vin(Max)(V): 5.5; Vin(Min)(V): 2.2
U51 U52 = PS8802-1: Manufacturer: Used in BOM report; SymbolVersion: use current date i.e. 2008-05-20; SymbolCreator: Use LDAP id; CompType: Used in some BOM reports.  Useful for finding later.; U/M: EA, IN, or GM
U53 = 23K640-I/SN: 64K SPI Bus Low-Power Serial SRAM, SOIC-8; Manufacturer: Microchip; SymbolCreator: Altium

## Sheet TIDA-00879_MISC.SchDoc: Hardware - Miscellaneous
size 431 x 279 mm; Date: Not shown in title block; ApprovedBy: Not shown in title block; CheckedBy: Not shown in title block; Author: Not shown in title block; CompanyName: Not shown in title block; DrawnBy: Russ Rosenquist; Engineer: Not shown in title block; Organization: Not shown in title block; Address1: Not shown in title block; Address2: Not shown in title block; Address3: Not shown in title block; Address4: Not shown in title block; DocumentNumber: 4; Revision: Use project parameter SCH_Rev; SheetNumber: 5; SheetTotal: 5; PageSetup: Record=PageOptions¦CenterHorizontal=True¦CenterVertical=True¦PrintScale=1.00¦XCorrection=1.00¦YCorrection=1.00¦PrintKind=0¦BorderSize=5000000¦LeftOffset=0¦BottomOffset=0¦Orientation=2¦PaperLength=1000¦PaperWidth=1000¦Scale=100¦PaperSource=15¦PrintQuality=600¦MediaType=1¦DitherType=10¦PaperKind=Letter¦PrintScaleMode=1
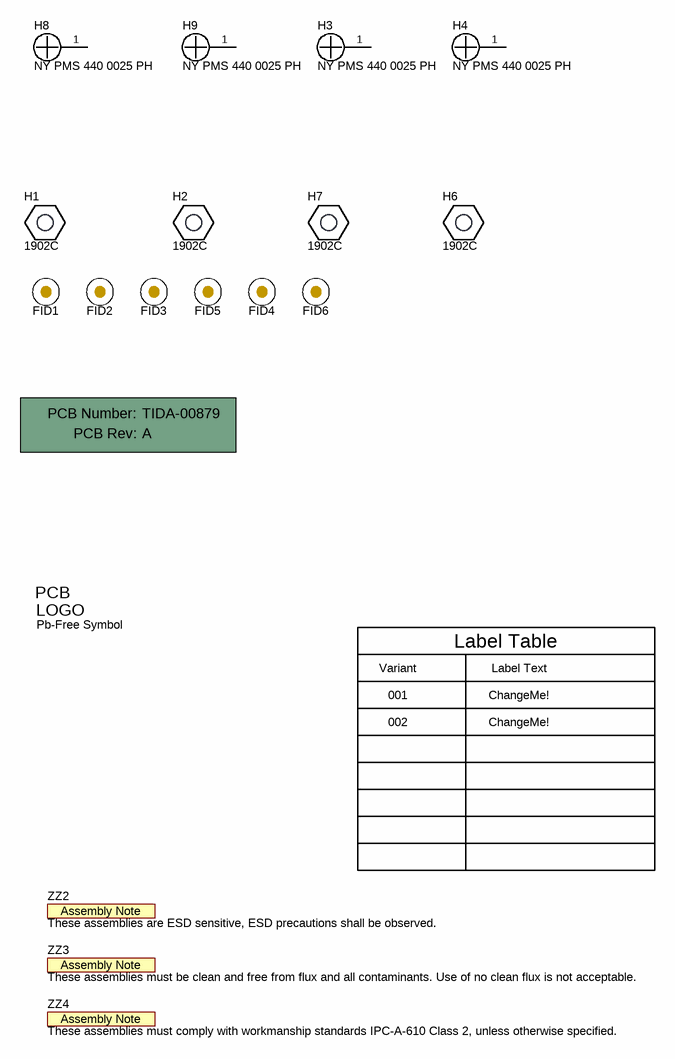
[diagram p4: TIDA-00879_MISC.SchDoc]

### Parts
!PCB1  Printed Circuit Board  (value not drawn)  (mechanical)
FID1  Fiducial  [Fiducial10-30]  (value not drawn)
FID2  Fiducial  [Fiducial10-30]  (value not drawn)
FID3  Fiducial  [Fiducial10-30]  (value not drawn)
FID4  Fiducial  [Fiducial10-30]  (value not drawn)
FID5  Fiducial  [Fiducial10-30]  (value not drawn)
FID6  Fiducial  [Fiducial10-30]  (value not drawn)
H1  1902C  [Keystone_1902C]
H2  1902C  [Keystone_1902C]
H3  NY PMS 440 0025 PH  [NY PMS 440 0025 PH]
H4  NY PMS 440 0025 PH  [NY PMS 440 0025 PH]
H6  1902C  [Keystone_1902C]
H7  1902C  [Keystone_1902C]
H8  NY PMS 440 0025 PH  [NY PMS 440 0025 PH]
H9  NY PMS 440 0025 PH  [NY PMS 440 0025 PH]
Logo2  Pb-Free Symbol  [Pb-Free_Overlay_Small]  (no BOM)
ZZ2  These assemblies are ESD sensitive, ESD precautions shall be observed.  [AssemblyNote]  (no BOM)
ZZ3  These assemblies must be clean and free from flux and all contaminants. Use of no clean flux is not acceptable.  [AssemblyNote]  (no BOM)
ZZ4  These assemblies must comply with workmanship standards IPC-A-610 Class 2, unless otherwise specified.  [AssemblyNote]  (no BOM)

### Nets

Not connected (* = marked no-connect by the designer): H3 1; H4 1; H8 1; H9 1

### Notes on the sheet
- Variant
- Label Table
- Label Text
- 001
- 002
- ChangeMe!

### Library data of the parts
!PCB1 = PCB: Manufacturer: Any; PartNumber: TIDA-00879; SymbolCreator: a0412235
FID1-FID6 = Fiducial: Fiducial mark.  There is nothing to buy or mount.; SymbolCreator: codlsc
H1 H2 H6 H7 = 1902C: Standoff, Hex, 0.5"L #4-40 Nylon; Manufacturer: Keystone; SymbolCreator: a0412235; CompType: Hardware
H3 H4 H8 H9 = NY PMS 440 0025 PH: Machine Screw, Round, #4-40 x 1/4, Nylon, Philips panhead; Manufacturer: B&F Fastener Supply; CompType: Hardware; SymbolCreator: codlsc; U/M: EA
Logo2 = Pb-Free: SymbolCreator: a0412235
ZZ2-ZZ4 = AssemblyNote: SymbolCreator: codlsc

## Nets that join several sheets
AGND: TIDA-00879_MCU (9 pins), TIDA-00879_AFE (13 pins)
AVCC: TIDA-00879_MCU (C8.2 R5.2), TIDA-00879_AFE (11 pins)
DGND: TIDA-00879_MCU (33 pins), TIDA-00879_TEST (9 pins)
VIN: TIDA-00879_MCU (5 pins), TIDA-00879_TEST (C55.1 U50.1)
CS: TIDA-00879_MCU (U1.14), TIDA-00879_TEST (U53.1)
I+: TIDA-00879_MCU (U1.3), TIDA-00879_AFE (F1.2 R23.2)
I-: TIDA-00879_MCU (U1.4), TIDA-00879_AFE (R36.1)
IRANGE_SEL: TIDA-00879_MCU (U1.44), TIDA-00879_AFE (U13.4 U13.8)
RXD: TIDA-00879_MCU (U1.27), TIDA-00879_TEST (R50.2 R57.1 U51.6)
SCLK: TIDA-00879_MCU (U1.36), TIDA-00879_TEST (U53.6)
SIMO: TIDA-00879_MCU (U1.17), TIDA-00879_TEST (U53.5)
SOMI: TIDA-00879_MCU (U1.16), TIDA-00879_TEST (U53.2)
TEST_EN: TIDA-00879_MCU (U1.37), TIDA-00879_TEST (U50.3)
TXD: TIDA-00879_MCU (U1.28), TIDA-00879_TEST (R53.1)
v+: TIDA-00879_MCU (U1.1), TIDA-00879_AFE (9 pins)
V-: TIDA-00879_MCU (U1.2), TIDA-00879_AFE (R30.1)
VRANGE_0: TIDA-00879_MCU (U1.39), TIDA-00879_AFE (U5.6)
VRANGE_1: TIDA-00879_MCU (U1.43), TIDA-00879_AFE (U5.5)

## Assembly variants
001: not fitted C20 C26 C31 C36 FID1 FID2 FID3 FID4 FID5 FID6 R43 R44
